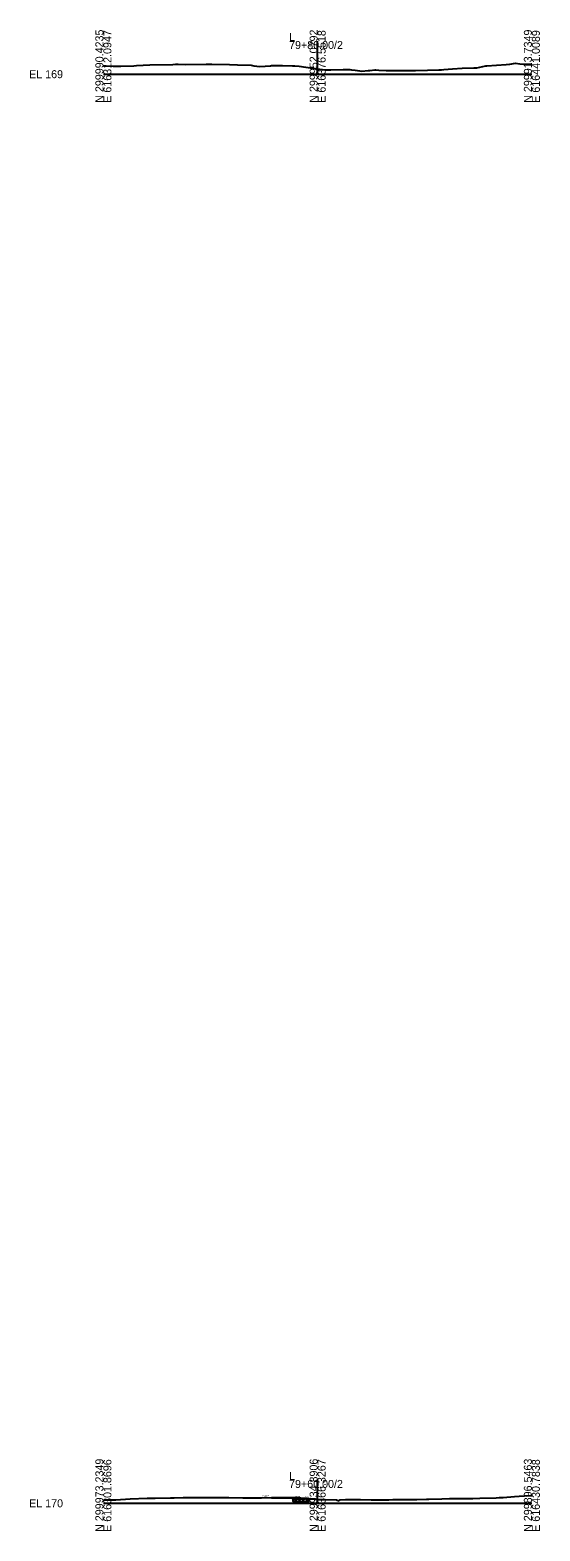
# Model space of a CAD drawing. Extents: x -81 to 616364, y 450 to 299952.
# Drawn here: x 552427 to 552605, y 118839 to 119364 of the extents above; entities that cross this region are included whole.
import ezdxf

# ---------------------------------------------------------------- set-up
doc = ezdxf.new("R2010")
doc.units = 0
for name, color, linetype in [('Exist XS Ground Line', 7, 'Continuous'), ('Old_Level_63', 7, 'Continuous'), ('Prop XS Dump Level', 7, 'Continuous'), ('Prop XS Earthwork Shape', 7, 'Continuous'), ('Prop XS Earthwork Undercut', 7, 'Continuous'), ('Prop XS Finish Grade', 7, 'Continuous'), ('Prop XS Finish Grade Pavement', 7, 'Continuous'), ('Prop XS Pvmt Edge Slope', 7, 'Continuous'), ('Prop XS SE Text', 7, 'Continuous'), ('Prop XS Side Slope Text', 7, 'Continuous'), ('Prop XS Subgrade Earthwork', 7, 'Continuous'), ('Prop XS Undercut Exc Hatch', 7, 'Continuous')]:
    doc.layers.add(name, color=color, linetype=linetype)

msp = doc.modelspace()

# ---------------------------------------------------------------- linework, layer by layer
at = {"layer": 'Exist XS Ground Line'}
for points in [[(552452.36, 119351.25), (552453.33, 119351.26), (552455.74, 119351.22), (552458.44, 119351.19), (552462.97, 119351.3), (552463.9, 119351.35), (552468.66, 119351.64), (552476.67, 119351.8), (552477.59, 119351.83), (552478.51, 119351.83), (552480.98, 119351.78), (552488.32, 119351.81), (552490.36, 119351.82), (552496.47, 119351.76), (552499.3, 119351.69), (552504.05, 119351.48), (552504.61, 119351.4), (552505.06, 119351.31), (552507.18, 119351.07), (552510.89, 119351.33), (552511.23, 119351.35), (552515.1, 119351.45), (552518.61, 119351.33), (552519.37, 119351.27), (552520.9, 119351.2), (552525.55, 119350.48), (552527.36, 119350.22), (552529.05, 119349.98), (552530.08, 119349.86), (552530.6, 119349.84), (552532, 119349.9), (552536.34, 119350.02), (552538.64, 119349.99), (552539.16, 119349.9), (552540.53, 119349.76), (552542.12, 119349.55), (552542.86, 119349.46), (552545.1, 119349.63), (552545.58, 119349.68), (552547.33, 119349.86), (552547.75, 119349.89), (552548.74, 119349.81), (552551.32, 119349.63), (552553.01, 119349.61), (552558.81, 119349.6), (552561.63, 119349.63), (552565.77, 119349.74), (552569.78, 119349.84), (552570.76, 119349.93), (552571.59, 119350), (552574.63, 119350.21), (552577.92, 119350.46), (552582, 119350.57), (552583.08, 119350.61), (552586.19, 119351.25), (552586.63, 119351.28), (552593.32, 119351.75), (552594.62, 119351.92), (552596.6, 119352.23), (552598.2, 119352), (552599.43, 119351.84), (552599.95, 119351.89), (552602.36, 119352.01)], [(552452.36, 118849.5), (552453.36, 118849.53), (552456.74, 118849.59), (552461.72, 118849.9), (552467.64, 118850.13), (552470.43, 118850.2), (552475.84, 118850.29), (552477.13, 118850.31), (552480.27, 118850.35), (552481.82, 118850.39), (552482.95, 118850.37), (552484.19, 118850.37), (552487.65, 118850.41), (552489.05, 118850.41), (552490.23, 118850.39), (552491.22, 118850.41), (552495.22, 118850.42), (552496.22, 118850.41), (552501.12, 118850.31), (552502.14, 118850.31), (552505.47, 118850.27), (552505.92, 118850.22), (552507.77, 118850.23), (552508.78, 118850.35), (552509.45, 118850.36), (552511.17, 118850.22), (552514.4, 118850.31), (552514.95, 118850.32), (552518.45, 118850.24), (552519.28, 118850.24), (552519.88, 118850.24), (552522.79, 118850.09), (552524.66, 118849.95), (552525.22, 118849.86), (552527.36, 118849.71), (552527.99, 118849.66), (552529.98, 118849.66), (552533.91, 118849.55), (552534.75, 118849.19), (552535.27, 118849.62), (552537.16, 118849.65), (552542.42, 118849.65), (552546.1, 118849.62), (552546.93, 118849.61), (552552.27, 118849.61), (552553.69, 118849.63), (552555.09, 118849.63), (552562.1, 118849.68), (552565.45, 118849.76), (552565.84, 118849.76), (552566.27, 118849.8), (552570.82, 118849.97), (552573.53, 118850.05), (552576.03, 118850.01), (552579.96, 118850.08), (552581.67, 118850.09), (552584.19, 118850.17), (552589.82, 118850.31), (552590.91, 118850.34), (552592.34, 118850.34), (552596.27, 118850.68), (552597.96, 118850.86), (552601.71, 118851.05), (552602.36, 118851.09)]]:
    msp.add_lwpolyline(points, dxfattribs=at)
at = {"layer": 'Old_Level_63'}
for p, q in [((552527.36, 119348.36), (552527.36, 119359.97)), ((552452.36, 119348.36), (552527.36, 119348.36)), ((552527.36, 119348.36), (552602.36, 119348.36)), ((552527.36, 118848.36), (552527.36, 118856.53)), ((552452.36, 118848.36), (552527.36, 118848.36)), ((552527.36, 118848.36), (552602.36, 118848.36))]:
    msp.add_line(p, q, dxfattribs=at)
at = {"layer": 'Prop XS Earthwork Shape'}
msp.add_lwpolyline([(552519.05, 118850.07), (552519.65, 118850.06), (552521.45, 118850.03), (552521.73, 118850.01), (552523.32, 118849.88), (552523.66, 118850.02), (552522.79, 118850.09), (552519.88, 118850.24), (552519.28, 118850.24), (552518.45, 118850.24), (552518.45, 118850.09)], close=True, dxfattribs=at)
at = {"layer": 'Prop XS Earthwork Undercut'}
msp.add_lwpolyline([(552518.65, 118850.08), (552518.65, 118849.08), (552519.03, 118849.07), (552519.63, 118849.06), (552521.43, 118849.03), (552523.84, 118848.98), (552524.26, 118848.95), (552524.26, 118849.96), (552523.26, 118849.99), (552521.45, 118850.03), (552519.65, 118850.06)], close=True, dxfattribs=at)
at = {"layer": 'Prop XS Finish Grade'}
for p, q in [((552521.52, 118850.22), (552523.32, 118850.08)), ((552523.32, 118850.08), (552523.66, 118850.02))]:
    msp.add_line(p, q, dxfattribs=at)
at = {"layer": 'Prop XS Finish Grade Pavement'}
for p, q in [((552514.95, 118850.32), (552511.17, 118850.22)), ((552520.91, 118850.23), (552514.95, 118850.32)), ((552520.91, 118850.23), (552521.52, 118850.22))]:
    msp.add_line(p, q, dxfattribs=at)
at = {"layer": 'Prop XS Pvmt Edge Slope'}
msp.add_line((552521.52, 118850.22), (552521.73, 118850.01), dxfattribs=at)
at = {"layer": 'Prop XS Subgrade Earthwork'}
for p, q in [((552518.45, 118850.09), (552518.45, 118850.24)), ((552518.45, 118850.09), (552519.05, 118850.07)), ((552519.05, 118850.07), (552519.65, 118850.06)), ((552521.45, 118850.03), (552519.65, 118850.06)), ((552521.45, 118850.03), (552521.73, 118850.01)), ((552521.73, 118850.01), (552523.32, 118849.88)), ((552523.32, 118849.88), (552523.66, 118850.02))]:
    msp.add_line(p, q, dxfattribs=at)
at = {"layer": 'Prop XS Undercut Exc Hatch'}
for p, q in [((552518.65, 118849.51), (552519.21, 118850.07)), ((552518.65, 118849.2), (552518.77, 118849.08)), ((552519.05, 118850.07), (552520.07, 118849.05)), ((552519.48, 118849.06), (552520.46, 118850.05)), ((552520.35, 118850.05), (552521.37, 118849.03)), ((552520.73, 118849.04), (552521.71, 118850.02)), ((552521.65, 118850.02), (552522.67, 118849)), ((552521.98, 118849.01), (552522.96, 118849.99)), ((552522.94, 118850), (552523.97, 118848.97)), ((552523.22, 118848.99), (552524.19, 118849.96)), ((552524.25, 118849.96), (552524.26, 118849.96))]:
    msp.add_line(p, q, dxfattribs=at)

# ---------------------------------------------------------------- texts
at = {"layer": 'Old_Level_63'}
for s, p in [('N 299990.4235', (552452.36, 119338.36)), ('E 616312.0947', (552455.16, 119338.36)), ('N 299952.0792', (552527.36, 119338.37)), ('E 616376.5518', (552530.16, 119338.37)), ('N 299913.7349', (552602.36, 119338.36)), ('E 616441.0089', (552605.16, 119338.36)), ('N 299973.2349', (552452.36, 118838.36)), ('E 616301.8696', (552455.16, 118838.36)), ('N 299934.8906', (552527.36, 118838.36)), ('E 616366.3267', (552530.16, 118838.36)), ('N 299896.5463', (552602.36, 118838.36)), ('E 616430.7838', (552605.16, 118838.37))]:
    msp.add_text(s, height=2.8, rotation=90, dxfattribs=at).set_placement(p)
for s, p in [('L', (552517.36, 119359.97)), ('79+80.00/2', (552517.37, 119357.17)), ('EL 169', (552426.36, 119346.96)), ('79+60.00/2', (552517.36, 118853.73)), ('L', (552517.36, 118856.53)), ('EL 170', (552426.37, 118846.96))]:
    msp.add_text(s, height=2.8, dxfattribs=at).set_placement(p)
at = {"layer": 'Prop XS Dump Level'}
msp.add_text('Case1', height=0.0122, dxfattribs=at).set_placement((552523.32, 118850.07))
at = {"layer": 'Prop XS SE Text'}
msp.add_text('EX. DRIVE', height=0.306, dxfattribs=at).set_placement((552508.14, 118850.8))
at = {"layer": 'Prop XS Side Slope Text'}
for s, p in [('170.86', (552526.36, 119349.22)), ('171.656', (552522.73, 118848.14))]:
    msp.add_text(s, height=0.5, dxfattribs=at).set_placement(p)
for s, rotation, p in [('EXIST.', 358.9585, (552519.23, 118850.41)), ('6.01:1', 350.5521, (552522.97, 118850.38))]:
    msp.add_text(s, height=0.5, rotation=rotation, dxfattribs=at).set_placement(p)

doc.saveas('drawing.dxf')
